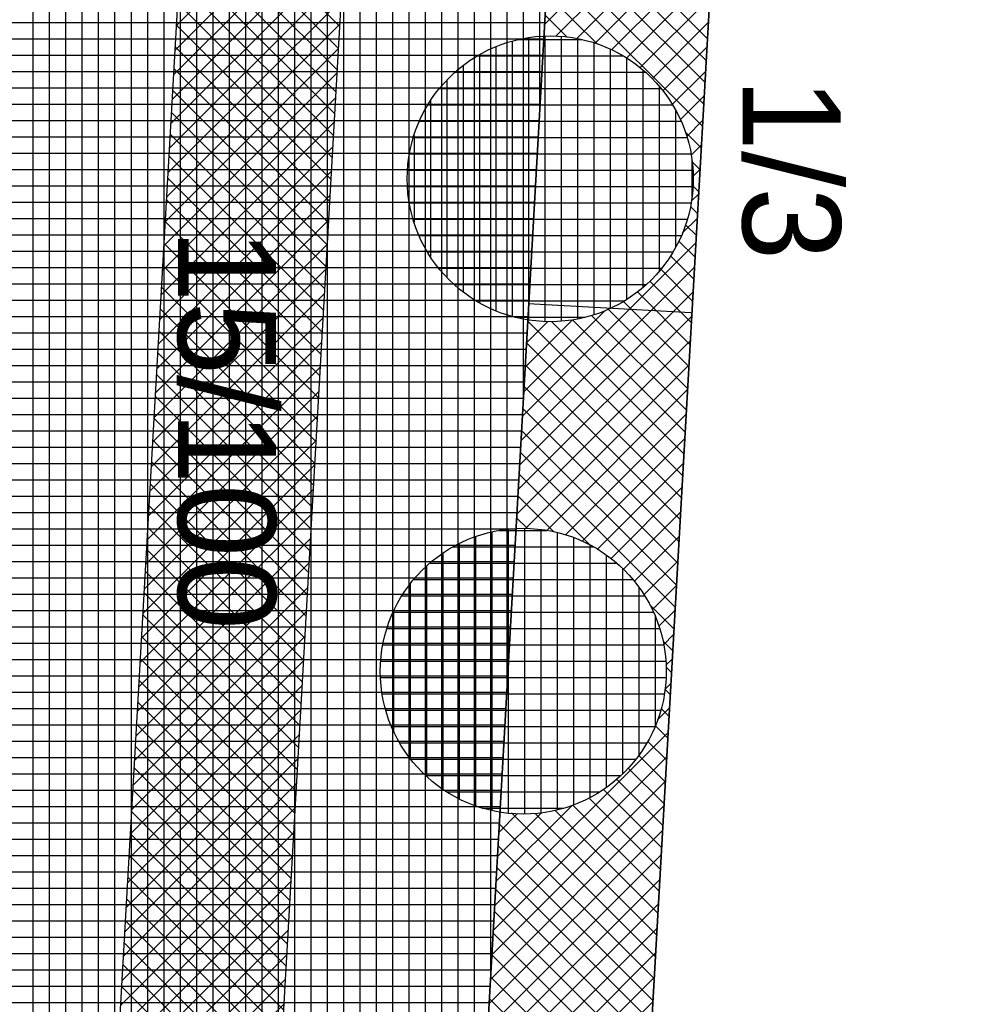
# Model space of a CAD drawing. Extents: x -565346 to -564154, y -1097386 to -1095620.
# Drawn here: x -564300.96 to -564289.4, y -1097289.41 to -1097277.36 of the extents above; entities that cross this region are included whole.
import ezdxf

# ---------------------------------------------------------------- set-up
doc = ezdxf.new("R2010")
doc.units = 0
for name, color, linetype in [('Vrstva 13', 7, 'Continuous'), ('Vrstva 40', 7, 'Continuous'), ('Vrstva 41', 7, 'Continuous'), ('Vrstva 42', 7, 'Continuous'), ('Vrstva 43', 7, 'Continuous'), ('Vrstva 44', 7, 'Continuous')]:
    doc.layers.add(name, color=color, linetype=linetype)

msp = doc.modelspace()

# ---------------------------------------------------------------- linework, layer by layer
at = {"layer": 'Vrstva 13'}
msp.add_line((-564291.2, -1097253.99), (-564294.24, -1097307.55), dxfattribs=at)
at = {"layer": 'Vrstva 41'}
msp.add_line((-564292.742, -1097280.947), (-564294.735, -1097280.834), dxfattribs=at)
msp.add_lwpolyline([(-564297.082, -1097322.329), (-564302.848, -1097333.175), (-564300.817, -1097333.615), (-564295.11, -1097322.88), (-564285.364, -1097151.156), (-564287.358, -1097151.043), (-564289.027, -1097180.417), (-564293.197, -1097253.877), (-564296.237, -1097307.437)], close=True, dxfattribs=at)
at = {"layer": 'Vrstva 42'}
for p, q in [((-564296.917, -1097275.308), (-564299.041, -1097277.432)), ((-564292.409, -1097275.289), (-564294.533, -1097277.413)), ((-564296.934, -1097275.608), (-564299.058, -1097277.732)), ((-564298.934, -1097275.544), (-564297.038, -1097277.44)), ((-564292.426, -1097275.589), (-564294.395, -1097277.558)), ((-564294.435, -1097275.693), (-564292.54, -1097277.589)), ((-564298.949, -1097275.811), (-564297.053, -1097277.707)), ((-564296.951, -1097275.908), (-564299.075, -1097278.032)), ((-564294.45, -1097275.961), (-564292.555, -1097277.857)), ((-564292.443, -1097275.889), (-564294.14, -1097277.586)), ((-564298.965, -1097276.079), (-564297.069, -1097277.975)), ((-564296.968, -1097276.208), (-564299.092, -1097278.332)), ((-564294.466, -1097276.229), (-564292.57, -1097278.124)), ((-564292.46, -1097276.189), (-564293.915, -1097277.643)), ((-564298.98, -1097276.347), (-564297.084, -1097278.243)), ((-564296.985, -1097276.508), (-564299.109, -1097278.632)), ((-564294.481, -1097276.496), (-564292.585, -1097278.392)), ((-564292.477, -1097276.489), (-564293.713, -1097277.725)), ((-564298.995, -1097276.614), (-564297.099, -1097278.51)), ((-564297.002, -1097276.807), (-564299.126, -1097278.932)), ((-564294.496, -1097276.764), (-564292.6, -1097278.659)), ((-564292.494, -1097276.789), (-564293.531, -1097277.826)), ((-564299.01, -1097276.882), (-564297.114, -1097278.778)), ((-564294.511, -1097277.032), (-564293.89, -1097277.652)), ((-564297.019, -1097277.107), (-564299.143, -1097279.231)), ((-564299.025, -1097277.15), (-564297.129, -1097279.046)), ((-564292.511, -1097277.089), (-564293.367, -1097277.944)), ((-564294.526, -1097277.299), (-564294.258, -1097277.568)), ((-564297.036, -1097277.407), (-564299.16, -1097279.531)), ((-564299.04, -1097277.417), (-564297.145, -1097279.313)), ((-564292.528, -1097277.388), (-564293.218, -1097278.079)), ((-564299.056, -1097277.685), (-564297.16, -1097279.581)), ((-564292.545, -1097277.688), (-564293.086, -1097278.229)), ((-564297.053, -1097277.707), (-564299.177, -1097279.831)), ((-564297.07, -1097278.007), (-564299.195, -1097280.131)), ((-564299.071, -1097277.953), (-564297.175, -1097279.848)), ((-564292.562, -1097277.988), (-564292.97, -1097278.396)), ((-564299.086, -1097278.22), (-564297.19, -1097280.116)), ((-564292.579, -1097278.288), (-564292.871, -1097278.58)), ((-564297.087, -1097278.307), (-564299.212, -1097280.431)), ((-564299.101, -1097278.488), (-564297.205, -1097280.384)), ((-564297.104, -1097278.607), (-564299.229, -1097280.731)), ((-564292.596, -1097278.588), (-564292.794, -1097278.785)), ((-564299.116, -1097278.756), (-564297.221, -1097280.651)), ((-564292.812, -1097278.73), (-564292.616, -1097278.927)), ((-564292.613, -1097278.888), (-564292.74, -1097279.015)), ((-564297.121, -1097278.907), (-564299.246, -1097281.031)), ((-564299.132, -1097279.023), (-564297.236, -1097280.919)), ((-564292.728, -1097279.098), (-564292.631, -1097279.195)), ((-564297.138, -1097279.206), (-564299.263, -1097281.33)), ((-564292.63, -1097279.188), (-564292.716, -1097279.273)), ((-564299.147, -1097279.291), (-564297.251, -1097281.187)), ((-564292.647, -1097279.487), (-564292.738, -1097279.578)), ((-564292.719, -1097279.39), (-564292.646, -1097279.462)), ((-564297.156, -1097279.506), (-564299.28, -1097281.63)), ((-564299.162, -1097279.558), (-564297.266, -1097281.454)), ((-564292.748, -1097279.643), (-564292.661, -1097279.73)), ((-564297.173, -1097279.806), (-564299.297, -1097281.93)), ((-564299.177, -1097279.826), (-564297.281, -1097281.722)), ((-564292.664, -1097279.787), (-564292.848, -1097279.971)), ((-564292.808, -1097279.866), (-564292.676, -1097279.998)), ((-564299.192, -1097280.094), (-564297.296, -1097281.99)), ((-564292.681, -1097280.087), (-564294.805, -1097282.211)), ((-564292.891, -1097280.066), (-564292.692, -1097280.265)), ((-564297.19, -1097280.106), (-564299.314, -1097282.23)), ((-564292.992, -1097280.247), (-564292.707, -1097280.533)), ((-564297.207, -1097280.406), (-564299.331, -1097282.53)), ((-564299.208, -1097280.361), (-564297.312, -1097282.257)), ((-564292.698, -1097280.387), (-564294.822, -1097282.511)), ((-564293.112, -1097280.411), (-564292.722, -1097280.801)), ((-564293.247, -1097280.558), (-564292.737, -1097281.068)), ((-564299.223, -1097280.629), (-564297.327, -1097282.525)), ((-564292.715, -1097280.687), (-564294.839, -1097282.811)), ((-564293.398, -1097280.69), (-564292.752, -1097281.336)), ((-564297.224, -1097280.706), (-564299.348, -1097282.83)), ((-564293.566, -1097280.805), (-564292.768, -1097281.604)), ((-564299.238, -1097280.897), (-564297.342, -1097282.793)), ((-564293.797, -1097280.92), (-564294.788, -1097281.911)), ((-564293.751, -1097280.903), (-564292.783, -1097281.871)), ((-564297.241, -1097281.006), (-564299.365, -1097283.13)), ((-564292.732, -1097280.987), (-564294.856, -1097283.11)), ((-564294.19, -1097281.03), (-564294.771, -1097281.611)), ((-564294.494, -1097281.051), (-564294.754, -1097281.311)), ((-564294.739, -1097281.046), (-564292.843, -1097282.942)), ((-564294.449, -1097281.053), (-564292.828, -1097282.674)), ((-564294.19, -1097281.03), (-564292.813, -1097282.407)), ((-564293.959, -1097280.978), (-564292.798, -1097282.139)), ((-564299.253, -1097281.164), (-564297.357, -1097283.06)), ((-564297.258, -1097281.305), (-564299.382, -1097283.43)), ((-564292.75, -1097281.287), (-564294.873, -1097283.41)), ((-564294.754, -1097281.314), (-564292.859, -1097283.21)), ((-564299.268, -1097281.432), (-564297.372, -1097283.328)), ((-564297.275, -1097281.605), (-564299.399, -1097283.729)), ((-564294.769, -1097281.582), (-564292.874, -1097283.477)), ((-564292.767, -1097281.586), (-564294.766, -1097283.586)), ((-564299.284, -1097281.7), (-564297.388, -1097283.596)), ((-564297.292, -1097281.905), (-564299.416, -1097284.029)), ((-564294.785, -1097281.849), (-564292.889, -1097283.745)), ((-564292.784, -1097281.886), (-564294.507, -1097283.61)), ((-564299.299, -1097281.967), (-564297.403, -1097283.863)), ((-564294.8, -1097282.117), (-564292.904, -1097284.013)), ((-564297.309, -1097282.205), (-564299.433, -1097284.329)), ((-564299.314, -1097282.235), (-564297.418, -1097284.131)), ((-564292.801, -1097282.186), (-564294.278, -1097283.663)), ((-564294.815, -1097282.385), (-564292.919, -1097284.28)), ((-564297.326, -1097282.505), (-564299.45, -1097284.629)), ((-564299.329, -1097282.503), (-564297.433, -1097284.399)), ((-564292.818, -1097282.486), (-564294.072, -1097283.74)), ((-564294.83, -1097282.652), (-564292.935, -1097284.548)), ((-564297.343, -1097282.805), (-564299.467, -1097284.929)), ((-564299.344, -1097282.77), (-564297.448, -1097284.666)), ((-564292.835, -1097282.786), (-564293.887, -1097283.839)), ((-564294.845, -1097282.92), (-564293.977, -1097283.789)), ((-564297.36, -1097283.105), (-564299.484, -1097285.229)), ((-564299.36, -1097283.038), (-564297.464, -1097284.934)), ((-564292.852, -1097283.086), (-564293.72, -1097283.954)), ((-564294.861, -1097283.187), (-564294.425, -1097283.623)), ((-564299.375, -1097283.306), (-564297.479, -1097285.201)), ((-564297.377, -1097283.404), (-564299.501, -1097285.529)), ((-564294.876, -1097283.455), (-564294.744, -1097283.587)), ((-564292.869, -1097283.386), (-564293.57, -1097284.087)), ((-564299.39, -1097283.573), (-564297.494, -1097285.469)), ((-564297.394, -1097283.704), (-564299.518, -1097285.828)), ((-564292.886, -1097283.685), (-564293.435, -1097284.235)), ((-564299.405, -1097283.841), (-564297.509, -1097285.737)), ((-564297.411, -1097284.004), (-564299.535, -1097286.128)), ((-564292.903, -1097283.985), (-564293.317, -1097284.399)), ((-564299.42, -1097284.109), (-564297.524, -1097286.004)), ((-564297.428, -1097284.304), (-564299.552, -1097286.428)), ((-564292.92, -1097284.285), (-564293.216, -1097284.581)), ((-564299.435, -1097284.376), (-564297.54, -1097286.272)), ((-564293.249, -1097284.517), (-564292.95, -1097284.815)), ((-564297.445, -1097284.604), (-564299.569, -1097286.728)), ((-564299.451, -1097284.644), (-564297.555, -1097286.54)), ((-564292.937, -1097284.585), (-564293.134, -1097284.782)), ((-564297.462, -1097284.904), (-564299.586, -1097287.028)), ((-564299.466, -1097284.911), (-564297.57, -1097286.807)), ((-564292.954, -1097284.885), (-564293.076, -1097285.007)), ((-564293.083, -1097284.965), (-564292.965, -1097285.083)), ((-564297.479, -1097285.204), (-564299.603, -1097287.328)), ((-564299.481, -1097285.179), (-564297.585, -1097287.075)), ((-564292.971, -1097285.185), (-564293.048, -1097285.262)), ((-564293.047, -1097285.284), (-564292.98, -1097285.351)), ((-564297.496, -1097285.504), (-564299.62, -1097287.628)), ((-564299.496, -1097285.447), (-564297.6, -1097287.343)), ((-564292.988, -1097285.485), (-564293.06, -1097285.557)), ((-564293.06, -1097285.554), (-564292.995, -1097285.618)), ((-564299.511, -1097285.714), (-564297.616, -1097287.61)), ((-564297.513, -1097285.803), (-564299.637, -1097287.927)), ((-564293.005, -1097285.784), (-564293.151, -1097285.931)), ((-564293.107, -1097285.79), (-564293.011, -1097285.886)), ((-564299.527, -1097285.982), (-564297.631, -1097287.878)), ((-564293.178, -1097286.001), (-564293.026, -1097286.154)), ((-564297.53, -1097286.103), (-564299.654, -1097288.227)), ((-564293.022, -1097286.084), (-564295.146, -1097288.208)), ((-564299.542, -1097286.25), (-564297.646, -1097288.146)), ((-564293.27, -1097286.193), (-564293.041, -1097286.421)), ((-564293.38, -1097286.365), (-564293.056, -1097286.689)), ((-564297.547, -1097286.403), (-564299.671, -1097288.527)), ((-564293.039, -1097286.384), (-564295.163, -1097288.508)), ((-564299.557, -1097286.517), (-564297.661, -1097288.413)), ((-564293.509, -1097286.52), (-564293.071, -1097286.957)), ((-564297.564, -1097286.703), (-564299.688, -1097288.827)), ((-564293.056, -1097286.684), (-564295.18, -1097288.808)), ((-564293.653, -1097286.658), (-564293.086, -1097287.224)), ((-564299.572, -1097286.785), (-564297.676, -1097288.681)), ((-564293.813, -1097286.781), (-564293.102, -1097287.492)), ((-564294.187, -1097286.973), (-564293.132, -1097288.027)), ((-564293.99, -1097286.886), (-564293.117, -1097287.76)), ((-564297.581, -1097287.003), (-564299.705, -1097289.127)), ((-564299.587, -1097287.053), (-564297.691, -1097288.949)), ((-564293.073, -1097286.984), (-564295.197, -1097289.108)), ((-564294.197, -1097286.977), (-564295.129, -1097287.908)), ((-564294.571, -1097287.068), (-564295.112, -1097287.608)), ((-564294.863, -1097287.077), (-564295.095, -1097287.309)), ((-564294.939, -1097287.069), (-564293.178, -1097288.83)), ((-564294.649, -1097287.076), (-564293.162, -1097288.563)), ((-564294.403, -1097287.039), (-564293.147, -1097288.295)), ((-564295.088, -1097287.202), (-564293.193, -1097289.098)), ((-564297.598, -1097287.303), (-564299.722, -1097289.427)), ((-564299.603, -1097287.32), (-564297.707, -1097289.216)), ((-564293.09, -1097287.284), (-564295.214, -1097289.408)), ((-564295.104, -1097287.47), (-564293.208, -1097289.366)), ((-564297.615, -1097287.603), (-564299.739, -1097289.727)), ((-564299.618, -1097287.588), (-564297.722, -1097289.484)), ((-564293.107, -1097287.584), (-564295.137, -1097289.614)), ((-564295.119, -1097287.738), (-564293.223, -1097289.633)), ((-564297.632, -1097287.902), (-564299.756, -1097290.027)), ((-564299.633, -1097287.856), (-564297.737, -1097289.752)), ((-564293.124, -1097287.883), (-564294.876, -1097289.636)), ((-564295.134, -1097288.005), (-564293.238, -1097289.901)), ((-564299.648, -1097288.123), (-564297.752, -1097290.019)), ((-564297.649, -1097288.202), (-564299.773, -1097290.326)), ((-564295.149, -1097288.273), (-564293.254, -1097290.169)), ((-564293.141, -1097288.183), (-564294.644, -1097289.686)), ((-564299.663, -1097288.391), (-564297.767, -1097290.287)), ((-564297.666, -1097288.502), (-564299.79, -1097290.626)), ((-564295.164, -1097288.541), (-564293.269, -1097290.436)), ((-564293.158, -1097288.483), (-564294.435, -1097289.76)), ((-564299.679, -1097288.659), (-564297.783, -1097290.554)), ((-564293.175, -1097288.783), (-564294.247, -1097289.856)), ((-564297.683, -1097288.802), (-564299.807, -1097290.926)), ((-564295.18, -1097288.808), (-564293.284, -1097290.704)), ((-564299.694, -1097288.926), (-564297.798, -1097290.822)), ((-564297.7, -1097289.102), (-564299.824, -1097291.226)), ((-564295.195, -1097289.076), (-564294.557, -1097289.714)), ((-564293.192, -1097289.083), (-564294.079, -1097289.97)), ((-564299.709, -1097289.194), (-564297.813, -1097291.09)), ((-564295.21, -1097289.343), (-564294.926, -1097289.628)), ((-564293.209, -1097289.383), (-564293.927, -1097290.1)), ((-564297.717, -1097289.402), (-564299.841, -1097291.526))]:
    msp.add_line(p, q, dxfattribs=at)
msp.add_lwpolyline([(-564300.922, -1097310.531), (-564298.925, -1097310.644), (-564291.523, -1097180.275), (-564289.854, -1097150.901), (-564291.851, -1097150.788), (-564293.52, -1097180.162), (-564300.73, -1097307.182)], close=True, dxfattribs=at)
at = {"layer": 'Vrstva 43'}
for p, q in [((-564294.59, -1097278.421), (-564294.59, -1097154.926)), ((-564294.79, -1097281.945), (-564294.79, -1097158.449)), ((-564294.99, -1097285.469), (-564294.99, -1097161.972)), ((-564295.19, -1097288.993), (-564295.19, -1097165.495)), ((-564295.39, -1097292.517), (-564295.39, -1097169.017)), ((-564295.59, -1097296.041), (-564295.59, -1097172.54)), ((-564295.79, -1097299.565), (-564295.79, -1097176.063)), ((-564295.99, -1097303.088), (-564295.99, -1097179.586)), ((-564296.19, -1097306.612), (-564296.19, -1097183.108)), ((-564296.39, -1097310.136), (-564296.39, -1097186.631)), ((-564296.59, -1097313.66), (-564296.59, -1097190.154)), ((-564296.79, -1097317.184), (-564296.79, -1097193.677)), ((-564296.99, -1097320.708), (-564296.99, -1097197.2)), ((-564297.19, -1097322.532), (-564297.19, -1097200.722)), ((-564297.39, -1097322.908), (-564297.39, -1097204.245)), ((-564297.59, -1097323.285), (-564297.59, -1097207.768)), ((-564297.79, -1097323.661), (-564297.79, -1097211.291)), ((-564297.99, -1097324.037), (-564297.99, -1097214.814)), ((-564298.19, -1097324.413), (-564298.19, -1097218.336)), ((-564298.39, -1097324.789), (-564298.39, -1097221.859)), ((-564298.59, -1097325.166), (-564298.59, -1097225.382)), ((-564298.79, -1097325.542), (-564298.79, -1097228.905)), ((-564298.99, -1097325.918), (-564298.99, -1097232.427)), ((-564299.19, -1097326.294), (-564299.19, -1097235.95)), ((-564299.39, -1097326.67), (-564299.39, -1097239.473)), ((-564299.59, -1097327.047), (-564299.59, -1097242.996)), ((-564299.79, -1097327.423), (-564299.79, -1097246.519)), ((-564299.99, -1097327.799), (-564299.99, -1097250.041)), ((-564300.19, -1097328.175), (-564300.19, -1097253.564)), ((-564300.39, -1097328.551), (-564300.39, -1097257.087)), ((-564300.59, -1097328.928), (-564300.59, -1097260.61)), ((-564300.79, -1097329.304), (-564300.79, -1097264.133)), ((-564301.543, -1097277.39), (-564294.531, -1097277.39)), ((-564301.554, -1097277.59), (-564294.543, -1097277.59)), ((-564301.565, -1097277.79), (-564294.554, -1097277.79)), ((-564301.577, -1097277.99), (-564294.566, -1097277.99)), ((-564301.588, -1097278.19), (-564294.577, -1097278.19)), ((-564301.599, -1097278.39), (-564294.588, -1097278.39)), ((-564301.611, -1097278.59), (-564294.6, -1097278.59)), ((-564301.622, -1097278.79), (-564294.611, -1097278.79)), ((-564301.634, -1097278.99), (-564294.622, -1097278.99)), ((-564301.645, -1097279.19), (-564294.634, -1097279.19)), ((-564301.656, -1097279.39), (-564294.645, -1097279.39)), ((-564301.668, -1097279.59), (-564294.656, -1097279.59)), ((-564301.679, -1097279.79), (-564294.668, -1097279.79)), ((-564301.69, -1097279.99), (-564294.679, -1097279.99)), ((-564301.702, -1097280.19), (-564294.69, -1097280.19)), ((-564301.713, -1097280.39), (-564294.702, -1097280.39)), ((-564301.724, -1097280.59), (-564294.713, -1097280.59)), ((-564301.736, -1097280.79), (-564294.724, -1097280.79)), ((-564301.747, -1097280.99), (-564294.736, -1097280.99)), ((-564301.758, -1097281.19), (-564294.747, -1097281.19)), ((-564301.77, -1097281.39), (-564294.759, -1097281.39)), ((-564301.781, -1097281.59), (-564294.77, -1097281.59)), ((-564301.792, -1097281.79), (-564294.781, -1097281.79)), ((-564301.804, -1097281.99), (-564294.793, -1097281.99)), ((-564301.815, -1097282.19), (-564294.804, -1097282.19)), ((-564301.827, -1097282.39), (-564294.815, -1097282.39)), ((-564301.838, -1097282.59), (-564294.827, -1097282.59)), ((-564301.849, -1097282.79), (-564294.838, -1097282.79)), ((-564301.861, -1097282.99), (-564294.849, -1097282.99)), ((-564301.872, -1097283.19), (-564294.861, -1097283.19)), ((-564301.883, -1097283.39), (-564294.872, -1097283.39)), ((-564301.895, -1097283.59), (-564294.883, -1097283.59)), ((-564301.906, -1097283.79), (-564294.895, -1097283.79)), ((-564301.917, -1097283.99), (-564294.906, -1097283.99)), ((-564301.929, -1097284.19), (-564294.917, -1097284.19)), ((-564301.94, -1097284.39), (-564294.929, -1097284.39)), ((-564301.951, -1097284.59), (-564294.94, -1097284.59)), ((-564301.963, -1097284.79), (-564294.951, -1097284.79)), ((-564301.974, -1097284.99), (-564294.963, -1097284.99)), ((-564301.986, -1097285.19), (-564294.974, -1097285.19)), ((-564301.997, -1097285.39), (-564294.986, -1097285.39)), ((-564302.008, -1097285.59), (-564294.997, -1097285.59)), ((-564302.02, -1097285.79), (-564295.008, -1097285.79)), ((-564302.031, -1097285.99), (-564295.02, -1097285.99)), ((-564302.042, -1097286.19), (-564295.031, -1097286.19)), ((-564302.054, -1097286.39), (-564295.042, -1097286.39)), ((-564302.065, -1097286.59), (-564295.054, -1097286.59)), ((-564302.076, -1097286.79), (-564295.065, -1097286.79)), ((-564302.088, -1097286.99), (-564295.076, -1097286.99)), ((-564302.099, -1097287.19), (-564295.088, -1097287.19)), ((-564302.11, -1097287.39), (-564295.099, -1097287.39)), ((-564302.122, -1097287.59), (-564295.11, -1097287.59)), ((-564302.133, -1097287.79), (-564295.122, -1097287.79)), ((-564302.144, -1097287.99), (-564295.133, -1097287.99)), ((-564302.156, -1097288.19), (-564295.144, -1097288.19)), ((-564302.167, -1097288.39), (-564295.156, -1097288.39)), ((-564302.179, -1097288.59), (-564295.167, -1097288.59)), ((-564302.19, -1097288.79), (-564295.178, -1097288.79)), ((-564302.201, -1097288.99), (-564295.19, -1097288.99)), ((-564302.213, -1097289.19), (-564295.201, -1097289.19)), ((-564302.224, -1097289.39), (-564295.213, -1097289.39))]:
    msp.add_line(p, q, dxfattribs=at)
msp.add_lwpolyline([(-564283.37, -1096906.18), (-564284.87, -1096930.83), (-564282.373, -1096930.972), (-564294.286, -1097140.634), (-564296.782, -1097140.492), (-564297.42, -1097150.37), (-564294.347, -1097150.646), (-564303.226, -1097307.04), (-564304.096, -1097322.37), (-564304.399, -1097332.838), (-564302.848, -1097333.175), (-564297.082, -1097322.329), (-564293.197, -1097253.877), (-564289.027, -1097180.417), (-564287.358, -1097151.043), (-564285.364, -1097151.156), (-564284.798, -1097141.172), (-564286.791, -1097141.059), (-564274.888, -1096931.397), (-564272.899, -1096931.51), (-564271.475, -1096906.55)], dxfattribs=at)
at = {"layer": 'Vrstva 44'}
for p, q in [((-564294.53, -1097277.557), (-564294.53, -1097281.052)), ((-564294.33, -1097277.561), (-564294.33, -1097281.048)), ((-564295.13, -1097277.687), (-564295.13, -1097280.922)), ((-564294.93, -1097277.617), (-564294.93, -1097280.99)), ((-564294.854, -1097277.6), (-564294.072, -1097277.6)), ((-564294.73, -1097277.576), (-564294.73, -1097281.032)), ((-564294.13, -1097277.587), (-564294.13, -1097281.02)), ((-564293.93, -1097277.638), (-564293.93, -1097280.968)), ((-564295.356, -1097277.8), (-564293.574, -1097277.8)), ((-564295.33, -1097277.785), (-564295.33, -1097280.823)), ((-564293.73, -1097277.718), (-564293.73, -1097280.891)), ((-564295.53, -1097277.916), (-564295.53, -1097280.691)), ((-564293.53, -1097277.826), (-564293.53, -1097280.782)), ((-564295.629, -1097278), (-564293.3, -1097278)), ((-564293.33, -1097277.973), (-564293.33, -1097280.634)), ((-564295.73, -1097278.098), (-564295.73, -1097280.51)), ((-564293.13, -1097278.173), (-564293.13, -1097280.433)), ((-564295.82, -1097278.2), (-564293.108, -1097278.2)), ((-564295.962, -1097278.4), (-564292.968, -1097278.4)), ((-564295.93, -1097278.351), (-564295.93, -1097280.257)), ((-564292.93, -1097278.463), (-564292.93, -1097280.141)), ((-564296.065, -1097278.6), (-564292.863, -1097278.6)), ((-564296.13, -1097278.773), (-564296.13, -1097279.837)), ((-564296.138, -1097278.8), (-564292.79, -1097278.8)), ((-564296.186, -1097279), (-564292.743, -1097279)), ((-564292.73, -1097279.076), (-564292.73, -1097279.521)), ((-564296.211, -1097279.2), (-564292.719, -1097279.2)), ((-564296.211, -1097279.4), (-564292.718, -1097279.4)), ((-564296.187, -1097279.6), (-564292.74, -1097279.6)), ((-564296.141, -1097279.8), (-564292.788, -1097279.8)), ((-564296.069, -1097280), (-564292.861, -1097280)), ((-564295.966, -1097280.2), (-564292.962, -1097280.2)), ((-564295.826, -1097280.4), (-564293.103, -1097280.4)), ((-564295.638, -1097280.6), (-564293.289, -1097280.6)), ((-564295.369, -1097280.8), (-564293.556, -1097280.8)), ((-564294.892, -1097281), (-564294.037, -1097281)), ((-564294.98, -1097283.595), (-564294.98, -1097287.073)), ((-564294.78, -1097283.585), (-564294.78, -1097287.082)), ((-564294.58, -1097283.598), (-564294.58, -1097287.069)), ((-564295.38, -1097283.687), (-564295.38, -1097286.981)), ((-564295.18, -1097283.629), (-564295.18, -1097287.041)), ((-564295.092, -1097283.61), (-564294.505, -1097283.61)), ((-564294.38, -1097283.636), (-564294.38, -1097287.033)), ((-564294.18, -1097283.697), (-564294.18, -1097286.972)), ((-564295.65, -1097283.81), (-564293.937, -1097283.81)), ((-564295.58, -1097283.771), (-564295.58, -1097286.897)), ((-564293.98, -1097283.786), (-564293.98, -1097286.881)), ((-564295.78, -1097283.891), (-564295.78, -1097286.778)), ((-564293.78, -1097283.91), (-564293.78, -1097286.759)), ((-564295.98, -1097284.048), (-564295.98, -1097286.619)), ((-564295.935, -1097284.01), (-564293.652, -1097284.01)), ((-564293.58, -1097284.075), (-564293.58, -1097286.592)), ((-564296.18, -1097284.268), (-564296.18, -1097286.399)), ((-564296.133, -1097284.21), (-564293.453, -1097284.21)), ((-564293.38, -1097284.306), (-564293.38, -1097286.363)), ((-564296.278, -1097284.41), (-564293.31, -1097284.41)), ((-564296.386, -1097284.61), (-564293.202, -1097284.61)), ((-564296.38, -1097284.594), (-564296.38, -1097286.072)), ((-564293.18, -1097284.66), (-564293.18, -1097286.005)), ((-564296.462, -1097284.81), (-564293.125, -1097284.81)), ((-564296.512, -1097285.01), (-564293.076, -1097285.01)), ((-564296.539, -1097285.21), (-564293.05, -1097285.21)), ((-564296.542, -1097285.41), (-564293.047, -1097285.41)), ((-564296.521, -1097285.61), (-564293.066, -1097285.61)), ((-564296.476, -1097285.81), (-564293.111, -1097285.81)), ((-564296.406, -1097286.01), (-564293.182, -1097286.01)), ((-564296.309, -1097286.21), (-564293.281, -1097286.21)), ((-564296.172, -1097286.41), (-564293.416, -1097286.41)), ((-564295.99, -1097286.61), (-564293.598, -1097286.61)), ((-564295.733, -1097286.81), (-564293.856, -1097286.81)), ((-564295.296, -1097287.01), (-564294.296, -1097287.01))]:
    msp.add_line(p, q, dxfattribs=at)
for centre in [(-564294.464, -1097279.304), (-564294.794, -1097285.334)]:
    msp.add_circle(centre, 1.75, dxfattribs=at)

# ---------------------------------------------------------------- texts
at = {"layer": 'Vrstva 40'}
for s, p in [('1/3', (-564292.11, -1097278.07)), ('15/100', (-564299.02, -1097279.92))]:
    msp.add_text(s, height=1.2, rotation=270, dxfattribs=at).set_placement(p)

doc.saveas('drawing.dxf')
